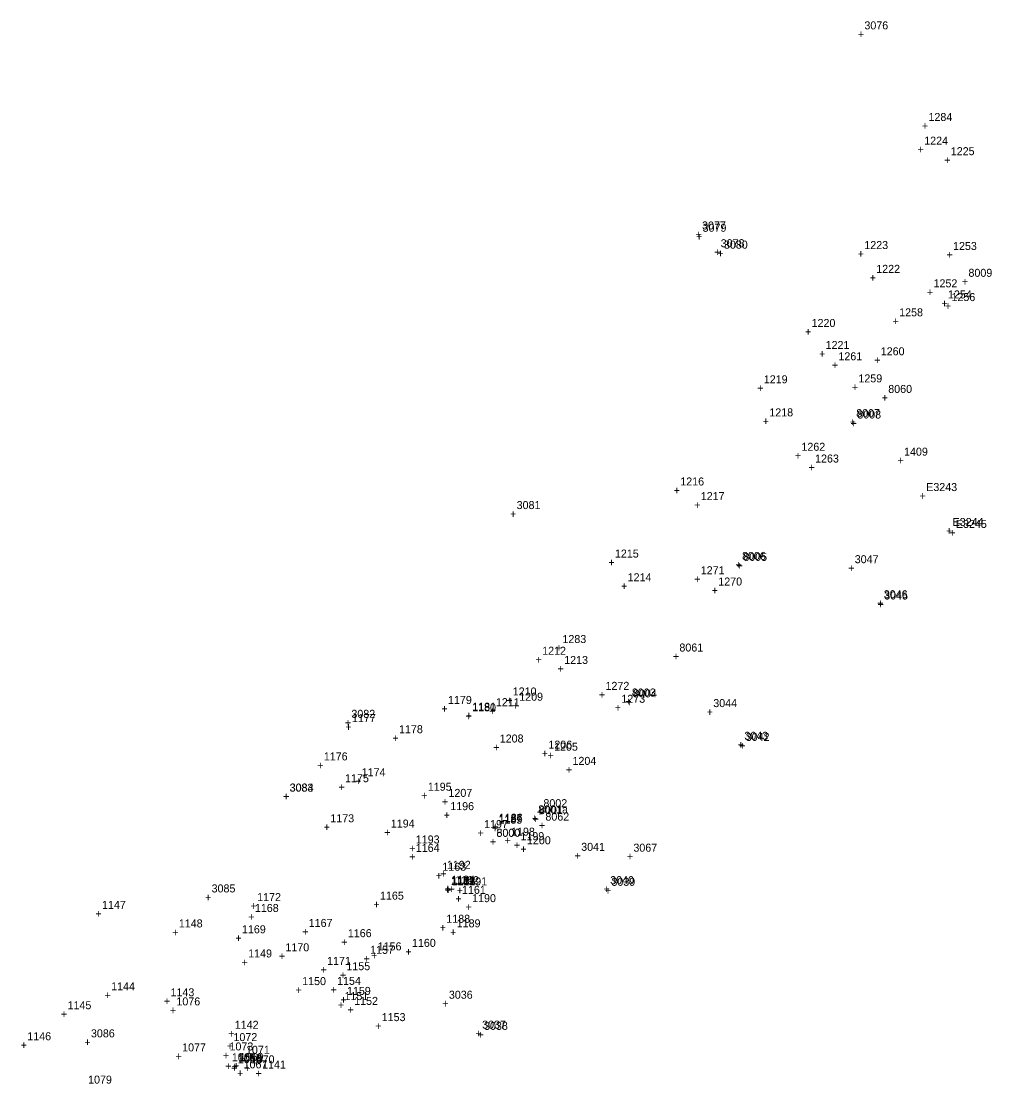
# Model space of a CAD drawing. Extents: x 1667192 to 1669644, y 336680 to 339991.
# Drawn here: x 1667709.5 to 1668012.8, y 338974.4 to 339306.3 of the extents above; entities that cross this region are included whole.
import ezdxf

# ---------------------------------------------------------------- set-up
doc = ezdxf.new("R2010")
doc.units = 0
for name, color, linetype in [('S_Control_BenchMark_Temp', 7, 'Continuous'), ('S_Control_Traverse_Point', 7, 'Continuous'), ('S_Curb_Type_1', 7, 'Continuous'), ('S_Curb_Type_5', 7, 'Continuous'), ('S_Drainage_CB', 7, 'Continuous'), ('S_Drainage_Culvert_Top', 7, 'Continuous'), ('S_Drainage_Ditch_Line', 7, 'Continuous'), ('S_Drainage_Invert', 7, 'Continuous'), ('S_Fencing_Page', 7, 'Continuous'), ('S_Ground_Elevation', 7, 'Continuous'), ('S_Property_IronPipeFound', 7, 'Continuous'), ('S_Roadway_Centerline', 7, 'Continuous'), ('S_Roadway_Drive_Gravel', 7, 'Continuous'), ('S_Roadway_Edge_Pavement', 7, 'Continuous'), ('S_Roadway_Edge_TW', 7, 'Continuous'), ('S_Roadway_Entr_Field_Wood', 7, 'Continuous'), ('S_Roadway_Monument', 7, 'Continuous'), ('S_Traffic_Sign_SinglePost', 7, 'Continuous'), ('S_Trees_TreeLine', 7, 'Continuous'), ('S_Utilities_GuyWire3', 7, 'Continuous'), ('S_Utilities_Pole_Power', 7, 'Continuous')]:
    doc.layers.add(name, color=color, linetype=linetype)

msp = doc.modelspace()

# ---------------------------------------------------------------- texts
at = {"layer": 'S_Control_BenchMark_Temp'}
for s, p in [('8000', (1667858.02, 339051.54)), ('+', (1667855.96, 339048.79))]:
    msp.add_text(s, height=2.5, dxfattribs=at).set_placement(p)
at = {"layer": 'S_Control_Traverse_Point'}
for s, p in [('500', (1667858.02, 339051.5)), ('500', (1667858.02, 339051.5)), ('500', (1667858.02, 339051.5)), ('500', (1667858.02, 339051.5)), ('500', (1667858.02, 339051.5)), ('500', (1667858.02, 339051.5)), ('500', (1667858.02, 339051.5)), ('500', (1667858.02, 339051.5)), ('500', (1667858.02, 339051.5)), ('500', (1667858.02, 339051.5)), ('500', (1667858.02, 339051.5)), ('500', (1667858.02, 339051.5)), ('+', (1667855.96, 339048.75)), ('+', (1667855.96, 339048.75)), ('+', (1667855.96, 339048.75)), ('+', (1667855.96, 339048.75)), ('+', (1667855.96, 339048.75)), ('+', (1667855.96, 339048.75)), ('+', (1667855.96, 339048.75)), ('+', (1667855.96, 339048.75)), ('+', (1667855.96, 339048.75)), ('+', (1667855.96, 339048.75)), ('+', (1667855.96, 339048.75)), ('+', (1667855.96, 339048.75))]:
    msp.add_text(s, height=2.5, dxfattribs=at).set_placement(p)
at = {"layer": 'S_Curb_Type_1'}
for s, p in [('8009', (1668005.54, 339226.46)), ('+', (1668003.48, 339223.71)), ('8007', (1667970.46, 339182.62)), ('+', (1667968.4, 339179.87)), ('8006', (1667934.79, 339138.01)), ('+', (1667932.73, 339135.27)), ('8003', (1667900.34, 339095.35)), ('+', (1667898.28, 339092.6)), ('8002', (1667872.69, 339060.78)), ('+', (1667870.63, 339058.03)), ('8001a', (1667871.07, 339058.85)), ('+', (1667869.01, 339056.1))]:
    msp.add_text(s, height=2.5, dxfattribs=at).set_placement(p)
at = {"layer": 'S_Curb_Type_5'}
for s, p in [('3045', (1667979.2, 339125.65)), ('+', (1667977.14, 339122.9)), ('3042', (1667935.92, 339081.48)), ('+', (1667933.86, 339078.73)), ('3039', (1667893.93, 339036.22)), ('+', (1667891.87, 339033.47)), ('3038', (1667854.13, 338991.22)), ('+', (1667852.07, 338988.47))]:
    msp.add_text(s, height=2.5, dxfattribs=at).set_placement(p)
at = {"layer": 'S_Drainage_CB'}
for s, p in [('3067', (1667900.81, 339046.87)), ('+', (1667898.75, 339044.12))]:
    msp.add_text(s, height=2.5, dxfattribs=at).set_placement(p)
at = {"layer": 'S_Drainage_Culvert_Top'}
for s, p in [('1181', (1667850.45, 339090.92)), ('+', (1667848.39, 339088.17)), ('1185', (1667858.65, 339055.63)), ('+', (1667856.59, 339052.88)), ('1184', (1667843.91, 339036.89)), ('+', (1667841.85, 339034.14)), ('1069', (1667777.74, 338981.51)), ('+', (1667775.68, 338978.76))]:
    msp.add_text(s, height=2.5, dxfattribs=at).set_placement(p)
at = {"layer": 'S_Drainage_Ditch_Line'}
for s, p in [('1066', (1667777.15, 338980.8)), ('+', (1667775.09, 338978.05))]:
    msp.add_text(s, height=2.5, dxfattribs=at).set_placement(p)
at = {"layer": 'S_Drainage_Invert'}
for s, p in [('1180', (1667850.42, 339090.7)), ('+', (1667848.36, 339087.95)), ('1186', (1667858.76, 339056.24)), ('+', (1667856.7, 339053.49)), ('1183', (1667844.02, 339036.4)), ('+', (1667841.96, 339033.65)), ('1068', (1667777.27, 338981.26)), ('+', (1667775.21, 338978.51))]:
    msp.add_text(s, height=2.5, dxfattribs=at).set_placement(p)
at = {"layer": 'S_Fencing_Page'}
for s, p in [('3076', (1667973.01, 339303.75)), ('+', (1667970.95, 339301)), ('3079', (1667922.44, 339240.53)), ('+', (1667920.38, 339237.78)), ('3080', (1667929.11, 339235.25)), ('+', (1667927.05, 339232.5)), ('3081', (1667864.32, 339153.9)), ('+', (1667862.26, 339151.15)), ('3082', (1667812.67, 339088.69)), ('+', (1667810.61, 339085.94)), ('3085', (1667768.98, 339034.15)), ('+', (1667766.92, 339031.4))]:
    msp.add_text(s, height=2.5, dxfattribs=at).set_placement(p)
at = {"layer": 'S_Ground_Elevation'}
for s, p in [('1224', (1667991.71, 339267.73)), ('+', (1667989.65, 339264.98)), ('1225', (1668000.01, 339264.45)), ('+', (1667997.95, 339261.7)), ('1223', (1667972.99, 339235.13)), ('+', (1667970.93, 339232.38)), ('1222', (1667976.72, 339227.69)), ('+', (1667974.66, 339224.94)), ('1252', (1667994.62, 339223.17)), ('+', (1667992.56, 339220.42)), ('1254', (1667999.13, 339219.7)), ('+', (1667997.07, 339216.95)), ('1220', (1667956.51, 339210.79)), ('+', (1667954.45, 339208.04)), ('1221', (1667960.89, 339203.91)), ('+', (1667958.83, 339201.16)), ('1219', (1667941.57, 339193.19)), ('+', (1667939.51, 339190.44)), ('1218', (1667943.3, 339182.86)), ('+', (1667941.24, 339180.11)), ('1262', (1667953.33, 339172.11)), ('+', (1667951.26, 339169.36)), ('1263', (1667957.6, 339168.44)), ('+', (1667955.54, 339165.7)), ('1216', (1667915.47, 339161.27)), ('+', (1667913.41, 339158.52)), ('1217', (1667921.86, 339156.71)), ('+', (1667919.8, 339153.96)), ('+', (1667892.98, 339136)), ('1215', (1667895.04, 339138.75)), ('1271', (1667921.86, 339133.54)), ('1214', (1667899.01, 339131.35)), ('+', (1667919.8, 339130.79)), ('1270', (1667927.35, 339130.02)), ('+', (1667896.95, 339128.6)), ('+', (1667925.29, 339127.27)), ('1212', (1667872.3, 339108.39)), ('+', (1667870.24, 339105.64)), ('+', (1667877.13, 339102.77)), ('1213', (1667879.19, 339105.52)), ('1272', (1667892.09, 339097.43)), ('1179', (1667842.87, 339093.03)), ('1211', (1667857.83, 339092.33)), ('+', (1667890.03, 339094.68)), ('1273', (1667897.05, 339093.39)), ('+', (1667840.81, 339090.28)), ('+', (1667855.77, 339089.58)), ('+', (1667894.99, 339090.64)), ('1208', (1667859.04, 339080.98)), ('+', (1667856.98, 339078.23)), ('1205', (1667876.02, 339078.43)), ('+', (1667873.96, 339075.68)), ('1204', (1667881.78, 339074)), ('1174', (1667815.89, 339070.45)), ('+', (1667879.72, 339071.25)), ('+', (1667813.83, 339067.7)), ('1207', (1667843.01, 339063.99)), ('+', (1667840.95, 339061.24)), ('1173', (1667806.09, 339056.06)), ('1187', (1667858.7, 339056)), ('+', (1667804.03, 339053.31)), ('+', (1667856.64, 339053.25)), ('1164', (1667832.8, 339046.83)), ('+', (1667830.74, 339044.08)), ('1163', (1667841.1, 339040.92)), ('+', (1667839.04, 339038.17)), ('1182', (1667843.8, 339036.52)), ('1162', (1667845.1, 339036.72)), ('+', (1667841.74, 339033.77)), ('+', (1667843.04, 339033.97)), ('1161', (1667847.24, 339033.7)), ('1172', (1667783.22, 339031.45)), ('1165', (1667821.61, 339031.89)), ('+', (1667845.18, 339030.95)), ('+', (1667781.16, 339028.7)), ('1168', (1667782.51, 339028.04)), ('+', (1667819.55, 339029.14)), ('+', (1667780.45, 339025.29)), ('1167', (1667799.33, 339023.37)), ('1169', (1667778.47, 339021.38)), ('+', (1667797.27, 339020.62)), ('1166', (1667811.56, 339020.17)), ('+', (1667776.4, 339018.63)), ('+', (1667809.5, 339017.42)), ('1156', (1667820.89, 339016.04)), ('1160', (1667831.6, 339017.14)), ('1170', (1667792.05, 339015.76)), ('+', (1667818.83, 339013.29)), ('+', (1667829.54, 339014.39)), ('+', (1667789.99, 339013.01)), ('1171', (1667805.07, 339011.52)), ('1155', (1667811.11, 339009.86)), ('+', (1667803.01, 339008.77)), ('+', (1667809.05, 339007.11)), ('1154', (1667808.2, 339005.28)), ('+', (1667806.14, 339002.53)), ('1159', (1667811.28, 339002.13)), ('1076', (1667757.98, 338998.86)), ('+', (1667809.22, 338999.38)), ('+', (1667755.92, 338996.11)), ('1072', (1667775.81, 338987.71)), ('1077', (1667759.77, 338984.49)), ('+', (1667773.75, 338984.96)), ('1073', (1667774.57, 338984.79)), ('1071', (1667779.72, 338983.74)), ('+', (1667757.71, 338981.74)), ('+', (1667772.51, 338982.04)), ('1065', (1667775.3, 338981.43)), ('+', (1667777.66, 338980.99)), ('1070', (1667781.21, 338980.75)), ('+', (1667773.24, 338978.68)), ('1067', (1667778.98, 338979.19)), ('+', (1667779.15, 338978)), ('1079', (1667730.38, 338974.42)), ('+', (1667776.92, 338976.44))]:
    msp.add_text(s, height=2.5, dxfattribs=at).set_placement(p)
at = {"layer": 'S_Property_IronPipeFound'}
for s, p in [('+', (1667791.34, 339062.92)), ('3083', (1667793.34, 339065.62)), ('3084', (1667793.4, 339065.67)), ('+', (1667791.28, 339062.87))]:
    msp.add_text(s, height=2.5, dxfattribs=at).set_placement(p)
at = {"layer": 'S_Roadway_Centerline'}
for s, p in [('3047', (1667969.99, 339137)), ('+', (1667967.93, 339134.25)), ('3044', (1667925.78, 339092.04)), ('+', (1667923.72, 339089.29)), ('3041', (1667884.5, 339047.14)), ('+', (1667882.44, 339044.39)), ('3036', (1667843.14, 339000.94)), ('+', (1667841.08, 338998.19))]:
    msp.add_text(s, height=2.5, dxfattribs=at).set_placement(p)
at = {"layer": 'S_Roadway_Drive_Gravel'}
for s, p in [('1147', (1667734.73, 339029.02)), ('+', (1667732.67, 339026.27)), ('1148', (1667758.74, 339023.22)), ('+', (1667756.68, 339020.47)), ('1149', (1667780.41, 339013.84)), ('+', (1667778.35, 339011.09)), ('1144', (1667737.59, 339003.56)), ('1150', (1667797.29, 339005.2)), ('+', (1667735.53, 339000.81)), ('1143', (1667756.14, 339001.71)), ('+', (1667795.23, 339002.45)), ('1151', (1667810.51, 339000.52)), ('1145', (1667723.96, 338997.66)), ('+', (1667754.08, 338998.96)), ('+', (1667808.45, 338997.77)), ('1152', (1667813.54, 338999.01)), ('+', (1667721.9, 338994.91)), ('+', (1667811.48, 338996.26)), ('1142', (1667776.22, 338991.55)), ('1146', (1667711.38, 338987.96)), ('+', (1667774.16, 338988.8)), ('+', (1667709.32, 338985.21)), ('1141', (1667784.76, 338979.11)), ('+', (1667782.7, 338976.36))]:
    msp.add_text(s, height=2.5, dxfattribs=at).set_placement(p)
at = {"layer": 'S_Roadway_Edge_Pavement'}
for s, p in [('1256', (1668000.23, 339218.88)), ('+', (1667998.17, 339216.13)), ('8008', (1667970.78, 339182.19)), ('+', (1667968.71, 339179.44)), ('E3245', (1668001.61, 339148.01)), ('+', (1667999.55, 339145.26)), ('8005', (1667935.15, 339137.72)), ('+', (1667933.08, 339134.97)), ('3046', (1667979.07, 339126.05)), ('+', (1667977.01, 339123.3)), ('8004', (1667900.7, 339095.06)), ('+', (1667898.64, 339092.31)), ('3043', (1667935.49, 339081.82)), ('+', (1667933.43, 339079.07)), ('8001', (1667871.34, 339058.6)), ('+', (1667869.28, 339055.85)), ('3040', (1667893.56, 339036.74)), ('+', (1667891.5, 339033.99)), ('1190', (1667850.41, 339031.11)), ('+', (1667848.35, 339028.37)), ('1188', (1667842.34, 339024.66)), ('+', (1667840.28, 339021.91)), ('3037', (1667853.53, 338991.59)), ('+', (1667851.47, 338988.84))]:
    msp.add_text(s, height=2.5, dxfattribs=at).set_placement(p)
at = {"layer": 'S_Roadway_Edge_TW'}
for s, p in [('8060', (1667980.47, 339190.18)), ('+', (1667978.41, 339187.43)), ('1409', (1667985.41, 339170.59)), ('+', (1667983.35, 339167.84)), ('E3243', (1667992.33, 339159.53)), ('+', (1667990.27, 339156.78)), ('+', (1667998.52, 339145.87)), ('E3244', (1668000.58, 339148.62)), ('8061', (1667915.19, 339109.4)), ('+', (1667913.13, 339106.65)), ('8062', (1667873.31, 339056.58)), ('+', (1667871.25, 339053.83)), ('1200', (1667867.54, 339049.19)), ('+', (1667865.48, 339046.44)), ('1189', (1667845.59, 339023.25)), ('+', (1667843.52, 339020.5)), ('1153', (1667822.15, 338993.95)), ('+', (1667820.09, 338991.2))]:
    msp.add_text(s, height=2.5, dxfattribs=at).set_placement(p)
at = {"layer": 'S_Roadway_Entr_Field_Wood'}
for s, p in [('1195', (1667836.56, 339065.92)), ('+', (1667834.5, 339063.17)), ('1196', (1667843.57, 339059.85)), ('+', (1667841.51, 339057.1)), ('1194', (1667824.99, 339054.42)), ('1197', (1667854.15, 339054.25)), ('+', (1667822.92, 339051.67)), ('1193', (1667832.8, 339049.45)), ('+', (1667852.09, 339051.5)), ('1198', (1667862.58, 339051.87)), ('1199', (1667865.51, 339050.47)), ('+', (1667830.74, 339046.7)), ('+', (1667860.52, 339049.12)), ('+', (1667863.45, 339047.72)), ('1192', (1667842.51, 339041.52)), ('+', (1667840.44, 339038.77)), ('1191', (1667847.65, 339036.34)), ('+', (1667845.59, 339033.59))]:
    msp.add_text(s, height=2.5, dxfattribs=at).set_placement(p)
at = {"layer": 'S_Roadway_Monument'}
for s, p in [('3077', (1667922.27, 339241.25)), ('+', (1667920.21, 339238.5)), ('3078', (1667928.1, 339235.7)), ('+', (1667926.04, 339232.95)), ('3086', (1667731.27, 338988.88)), ('+', (1667729.21, 338986.13))]:
    msp.add_text(s, height=2.5, dxfattribs=at).set_placement(p)
at = {"layer": 'S_Traffic_Sign_SinglePost'}
for s, p in [('1253', (1668000.72, 339234.84)), ('+', (1667998.66, 339232.09)), ('1258', (1667983.88, 339214.11)), ('+', (1667981.81, 339211.36)), ('1157', (1667818.53, 339014.97)), ('+', (1667816.47, 339012.22))]:
    msp.add_text(s, height=2.5, dxfattribs=at).set_placement(p)
at = {"layer": 'S_Trees_TreeLine'}
for s, p in [('1284', (1667993.04, 339275.13)), ('+', (1667990.98, 339272.38)), ('1283', (1667878.63, 339112.05)), ('+', (1667876.57, 339109.3)), ('1177', (1667812.85, 339087.37)), ('+', (1667810.79, 339084.62)), ('1178', (1667827.56, 339083.89)), ('+', (1667825.5, 339081.14)), ('1176', (1667804.05, 339075.38)), ('+', (1667801.99, 339072.63)), ('1175', (1667810.69, 339068.58)), ('+', (1667808.63, 339065.83))]:
    msp.add_text(s, height=2.5, dxfattribs=at).set_placement(p)
at = {"layer": 'S_Utilities_GuyWire3'}
for s, p in [('1260', (1667978.12, 339201.94)), ('1261', (1667964.89, 339200.38)), ('+', (1667976.06, 339199.19)), ('+', (1667962.83, 339197.63)), ('1210', (1667863.09, 339095.67)), ('+', (1667861.03, 339092.92)), ('1209', (1667865.13, 339094.03)), ('+', (1667863.07, 339091.28))]:
    msp.add_text(s, height=2.5, dxfattribs=at).set_placement(p)
at = {"layer": 'S_Utilities_Pole_Power'}
for s, p in [('1259', (1667971.14, 339193.48)), ('+', (1667969.08, 339190.73)), ('1206', (1667874.23, 339079.06)), ('+', (1667872.17, 339076.31))]:
    msp.add_text(s, height=2.5, dxfattribs=at).set_placement(p)

doc.saveas('drawing.dxf')
